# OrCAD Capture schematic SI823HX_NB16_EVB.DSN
size C; title: Si823Hx-NB16 Customer Evaluation Board - Schematic; rev: 1.0; note: SI823HX_NB16_EVB
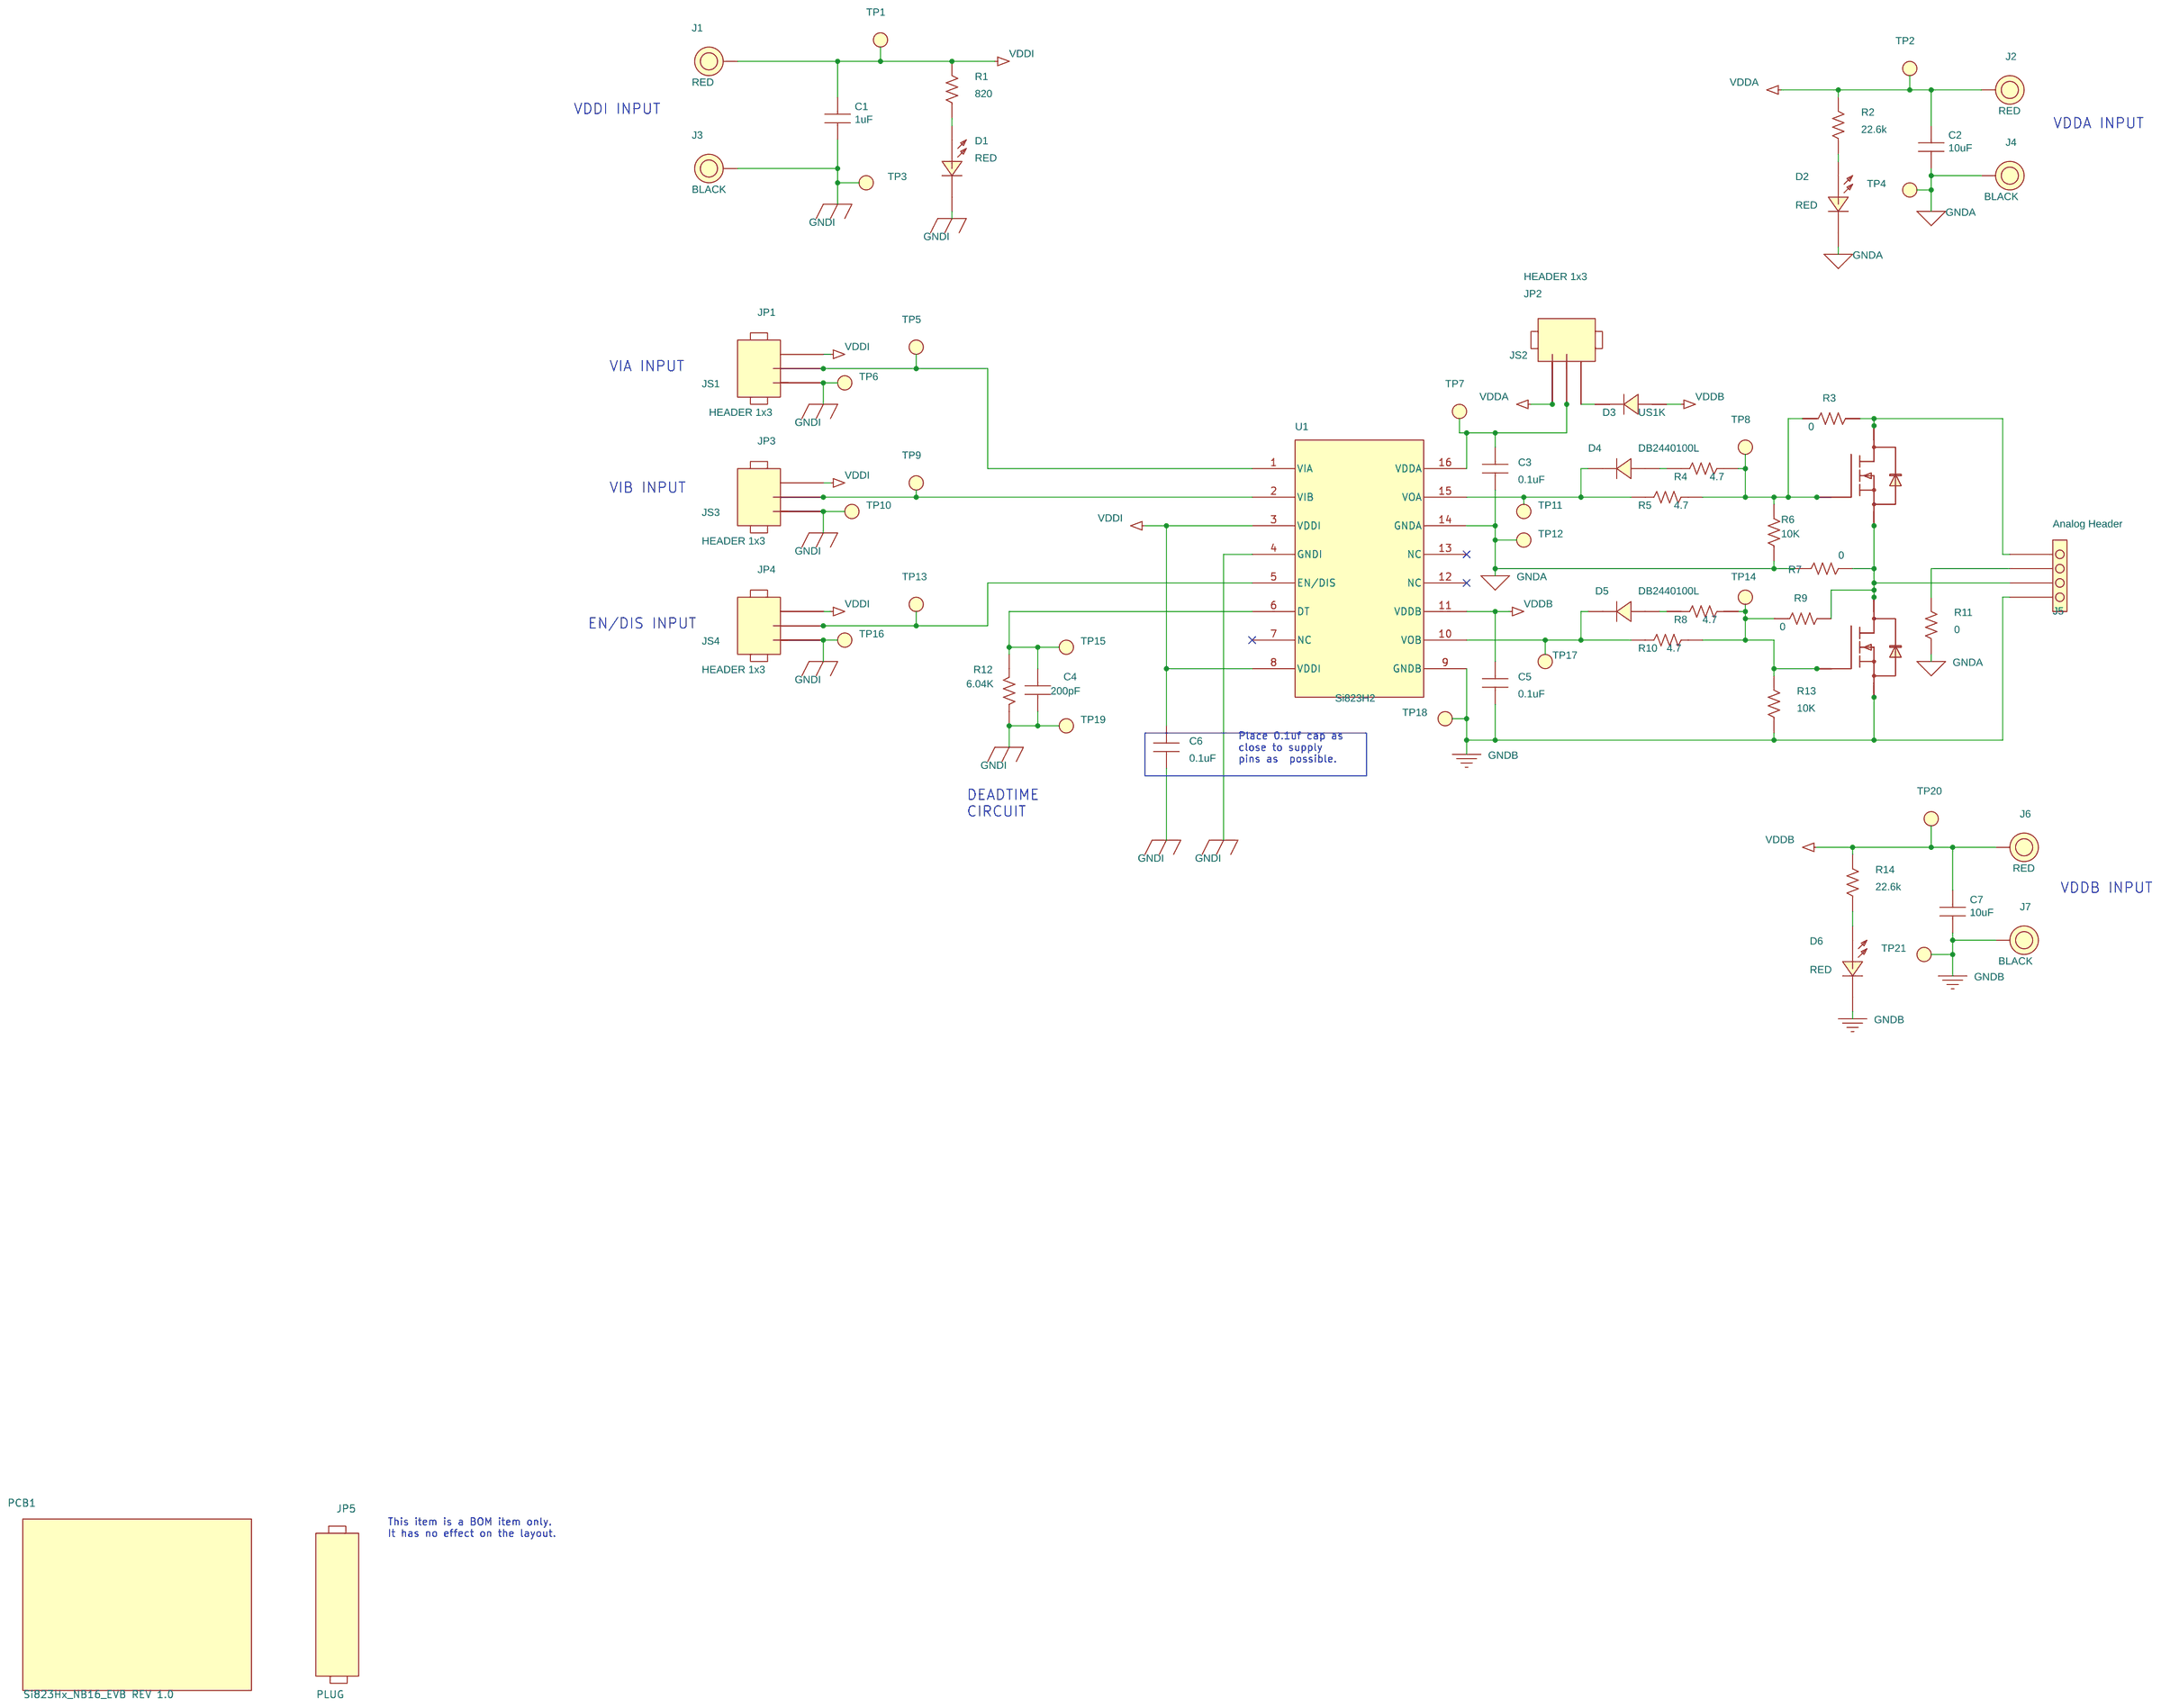
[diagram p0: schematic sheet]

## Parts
C1  1uF  [C0805]
C2  10uF  [C1210]
C3  0.1uF  [C1206]
C4  200pF  [C0805]
C5  0.1uF  [C1206]
C6  0.1uF  [C0805]
C7  10uF  [C1210]
D1  RED  [LED0603-KA]
D2  RED  [LED0603-KA]
D3  US1K  [DO-214AC]
D4  DB2440100L  [SOD-128]
D5  DB2440100L  [SOD-128]
D6  RED  [LED0603-KA]
J1  RED  [BINDING-POST]
J2  RED  [BINDING-POST]
J3  BLACK  [BINDING-POST]
J4  BLACK  [BINDING-POST]
J5  Analog Header  [CON1X4-1757268]
J6  RED  [BINDING-POST]
J7  BLACK  [BINDING-POST]
JP1  HEADER 1x3  [CONN-1X3]
JP2  HEADER 1x3  [CONN-1X3]
JP3  HEADER 1x3  [CONN-1X3]
JP4  HEADER 1x3  [CONN-1X3]
JP5  PLUG
JS1  Jumper Shunt  [SHUNT]
JS2  Jumper Shunt  [SHUNT]
JS3  Jumper Shunt  [SHUNT]
JS4  Jumper Shunt  [SHUNT]
PCB1  Si823Hx_NB16_EVB REV 1.0  [N/A]
R1  820  [R0402]
R2  22.6k  [R0402]
R3  0  [R0805]
R4  4.7  [R0805]
R5  4.7  [R0805]
R6  10K  [R0805]
R7  0  [R0805]
R8  4.7  [R0805]
R9  0  [R0805]
R10  4.7  [R0805]
R11  0  [R0805]
R12  6.04K  [R0805]
R13  10K  [R0805]
R14  22.6k  [R0402]
TP1  WHITE  [TESTPOINT]
TP2  WHITE  [TESTPOINT]
TP3  WHITE  [TESTPOINT]
TP4  WHITE  [TESTPOINT]
TP5  WHITE  [TESTPOINT]
TP6  WHITE  [TESTPOINT]
TP7  WHITE  [TESTPOINT]
TP8  WHITE  [TESTPOINT]
TP9  WHITE  [TESTPOINT]
TP10  WHITE  [TESTPOINT]
TP11  WHITE  [TESTPOINT]
TP12  WHITE  [TESTPOINT]
TP13  WHITE  [TESTPOINT]
TP14  WHITE  [TESTPOINT]
TP15  WHITE  [TESTPOINT]
TP16  WHITE  [TESTPOINT]
TP17  WHITE  [TESTPOINT]
TP18  WHITE  [TESTPOINT]
TP19  WHITE  [TESTPOINT]
TP20  WHITE  [TESTPOINT]
TP21  WHITE  [TESTPOINT]
U1  Si823H2  [SO16N6.0P1.27]
U3  SPD01N60C3  [DPAK-G2SD]
U4  IRF520  [TO-220_ALT]
U5  SPD01N60C3  [DPAK-G2SD]
U6  IRF520  [TO-220_ALT]

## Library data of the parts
C1 = CAP_NP: CAP, 1uF, 50V, ±10%, X7R, 0805; Manufacturer: Samsung; ManufacturerPN: CL21B105KBFNNNE; Part_Type: CAP/NP/MLCC; SiLabsPN: C0805X7R500-105K; Tolerance: ±10%; Type: X7R; Voltage: 50V; Datasheet: CL21B105KBFNNNE.pdf
C2 C7 = CAP_NP: CAP, 10uF, 50V, ±20%, X7R, 1210; Manufacturer: Venkel; ManufacturerPN: C1210X7R500-106M; Part_Type: CAP/NP/MLCC; SiLabsPN: C1210X7R500-106M; Tolerance: ±20%; Type: X7R; Voltage: 50V; Datasheet: PID_C.pdf
C3 C5 = CAP_NP: CAP, 0.1uF, 100V, ±20%, X7R, 1206; Manufacturer: Venkel; ManufacturerPN: C1206X7R101-104M; Part_Type: CAP/NP/MLCC; SiLabsPN: C1206X7R101-104M; Tolerance: ±20%; Type: X7R; Voltage: 100V; Datasheet: PID_C.pdf
C4 = CAP_NP: CAP, 200pF, 50V, ±10%, C0G, 0805; Manufacturer: Venkel; ManufacturerPN: C0805C0G500-201K; Part_Type: CAP/NP/MLCC; SiLabsPN: C0805C0G500-201K; Tolerance: ±10%; Type: C0G; Voltage: 50V; Datasheet: PID_C.pdf
C6 = CAP_NP: CAP, 0.1uF, 50V, ±10%, X7R, 0805; Manufacturer: Venkel; ManufacturerPN: C0805X7R500-104K; Part_Type: CAP/NP/MLCC; SiLabsPN: C0805X7R500-104K; Tolerance: ±10%; Type: X7R; Voltage: 50V; Datasheet: PID_C.pdf
D1 D2 D6 = LED: LED, RED, 631nM, 20mA, 2V, 54mcd, 0603; Manufacturer: LITE-ON TECHNOLOGY CORP; ManufacturerPN: LTST-C190KRKT; Part_Type: OPTO/LED; SiLabsPN: LTST-C190KRKT; Datasheet: P_100_LTST-C190KRKT.pdf
D3 = DIODE: DIO, SWITCH, ULTRA FAST, 800V, 1.0A, SMA; DISTRIBUTOR: Digi-Key; DIST_PN: US1K-FDICT-ND; MFG: Diodes Inc; MFG_PartNum: US1K-13-F; Manufacturer: Diodes Inc.; ManufacturerPN: US1K-13-F; Part_Type: DIO/SMT; Rating: 1.0A; SiLabsPN: US1K-13-F; Type: Switch, Ultra Fast; Voltage: 800V; Datasheet: ds16008.pdf
D4 D5 = DIODE: DIO, FAST, 40V, 1.0A, SOD-128; Manufacturer: Panasonic; Part_Type: DIO/SMT; Rating: 1.0A; Type: FAST; Voltage: 40V; Datasheet: DB2440100L.pdf
J1 = BINDING-POST: BINDING POST, Insulated, RED; Manufacturer: Johnson/Emerson; ManufacturerPN: 111-0702-001; Part_Type: CON; Rating: 15A; SiLabsPN: 111-0702-001; Silk: VDDI+; Type: BANANA; Datasheet: 111-0702-001.pdf
J2 = BINDING-POST: BINDING POST, Insulated, RED; Manufacturer: Johnson/Emerson; ManufacturerPN: 111-0702-001; Part_Type: CON; Rating: 15A; SiLabsPN: 111-0702-001; Silk: VDDA; Type: BANANA; Datasheet: 111-0702-001.pdf
J3 = BINDING-POST: BINDING POST, Insulated, BLACK; Manufacturer: Johnson/Emerson; ManufacturerPN: 111-0703-001; Part_Type: CON; Rating: 15A; SiLabsPN: 111-0703-001; Silk: GNDI; Type: BANANA; Datasheet: 111-0703-001.pdf
J4 = BINDING-POST: BINDING POST, Insulated, BLACK; Manufacturer: Johnson/Emerson; ManufacturerPN: 111-0703-001; Part_Type: CON; Rating: 15A; SiLabsPN: 111-0703-001; Silk: GNDA; Type: BANANA; Datasheet: 111-0703-001.pdf
J5 = ANALOG-HDR1X4: CONN, TERM HDR 4POS, 5.08MM, RT PCB; Manufacturer: PHOENIX CONTACT; ManufacturerPN: 1757268; Part_Type: CON; SiLabsPN: 1757268; Silk: VDD; Type: TERM HDR; Datasheet: 1757268.pdf
J6 = BINDING-POST: BINDING POST, Insulated, RED; Manufacturer: Johnson/Emerson; ManufacturerPN: 111-0702-001; Part_Type: CON; Rating: 15A; SiLabsPN: 111-0702-001; Silk: VDDB; Type: BANANA; Datasheet: 111-0702-001.pdf
J7 = BINDING-POST: BINDING POST, Insulated, BLACK; Manufacturer: Johnson/Emerson; ManufacturerPN: 111-0703-001; Part_Type: CON; Rating: 15A; SiLabsPN: 111-0703-001; Silk: GNDB; Type: BANANA; Datasheet: 111-0703-001.pdf
JP1-JP4 = CONN_HEADER_3: Header, 3x1, 0.1in pitch, Tin Plated; Manufacturer: Samtec; ManufacturerPN: TSW-103-07-T-S; Part_Type: CON/HEADER; SiLabsPN: TSW-103-07-T-S; Type: Header; Datasheet: TSW_TH.PDF
JP5 = CONN_TRBLK_9_MATE: CONN, TERM BLOCK, 4POS PLUG, 5.08MM; Manufacturer: Phoenix Contact; ManufacturerPN: 1757035; Part_Type: CON; SiLabsPN: 1757035; Type: TERM BLK; Datasheet: 1757035.pdf
JS1-JS4 = JMPR_SHUNT_SHORT_SIDES: Shunt, 1x2, 0.1in pitch, Tin plating; Manufacturer: Samtec; ManufacturerPN: SNT-100-BK-T; Part_Type: CON/SHUNT; SiLabsPN: SNT-100-BK-T; Type: Shunt; Datasheet: SNT.pdf
PCB1 = PCB: PCB, BARE BOARD, Si823Hx_NB16_EVB REV 1.0; Manufacturer: Skyworks; Part_Type: PCB/APS/Isolation; Type: BARE PCB
R1 = RES: RES, 820 Ohm, 1/16W, ±1%, ThickFilm, 0402; Manufacturer: Venkel; ManufacturerPN: CR0402-16W-8200FT; Part_Type: RES/SMT/ThickFilm; Rating: 1/16W; SiLabsPN: CR0402-16W-8200F; Tolerance: ±1%; Type: ThickFilm; Datasheet: PID_CR.pdf
R2 R14 = RES: RES, 22.6k, 1/16W, ±1%, ThickFilm, 0402; Manufacturer: Venkel; ManufacturerPN: CR0402-16W-2262F; Part_Type: RES/SMT/ThickFilm; Rating: 1/16W; SiLabsPN: CR0402-16W-2262F; Tolerance: ±1%; Type: ThickFilm; Datasheet: PID_CR.pdf
R3 R7 R9 R11 = RES: RES, 0 Ohm, 2A, ThickFilm, 0805; Manufacturer: Venkel; ManufacturerPN: CR0805-10W-000; Part_Type: RES/SMT/ThickFilm; Rating: 2A; SiLabsPN: CR0805-10W-000; Type: ThickFilm; Datasheet: PID_CR.pdf
R4 R5 R8 R10 = R: RES, 4.7 Ohm, 1/10W, ±5%, ThickFilm, 0805; Manufacturer: Venkel; ManufacturerPN: CR0805-10W-4R7J; Part_Type: RES/SMT/ThickFilm; Rating: 1/10W; SiLabsPN: CR0805-10W-4R7J; Tolerance: ±5%; Type: ThickFilm; Datasheet: PID_CR.pdf
R6 R13 = RES: RES, 10K, 1/8W, ±1%, ThickFilm, 0805; Manufacturer: Venkel; ManufacturerPN: CR0805-8W-1002F; Part_Type: RES/SMT/ThickFilm; Rating: 1/8W; SiLabsPN: CR0805-8W-1002F; Tolerance: ±1%; Type: ThickFilm; Datasheet: PID_CR.pdf
R12 = R: RES, 6.04K, 1/10W, ±1%, ThickFilm, 0805; DISTRIBUTOR: Digi-Key; DIST_PN: P150CCT-ND; MFG: Panasonic; MFG_PartNum: ERJ-6ENF1500V; Manufacturer: Venkel; ManufacturerPN: CR0805-10W-6041F; Part_Type: RES/SMT/ThickFilm; Rating: 1/10W; SiLabsPN: CR0805-10W-6041F; Tolerance: ±1%; Type: ThickFilm; Datasheet: PID_CR.pdf
TP1 = TEST_POINT: TESTPOINT, WHITE, PTH; Manufacturer: Kobiconn; ManufacturerPN: 151-201-RC; SiLabsPN: 151-201; Silk: VDDI; Type: Loop; Datasheet: KC-300780.pdf
TP2 = TEST_POINT: TESTPOINT, WHITE, PTH; Manufacturer: Kobiconn; ManufacturerPN: 151-201-RC; SiLabsPN: 151-201; Silk: VDDA; Type: Loop; Datasheet: KC-300780.pdf
TP3 TP6 TP10 TP16 TP19 = TEST_POINT: TESTPOINT, WHITE, PTH; Manufacturer: Kobiconn; ManufacturerPN: 151-201-RC; SiLabsPN: 151-201; Silk: GNDI; Type: Loop; Datasheet: KC-300780.pdf
TP4 TP12 = TEST_POINT: TESTPOINT, WHITE, PTH; Manufacturer: Kobiconn; ManufacturerPN: 151-201-RC; SiLabsPN: 151-201; Silk: GNDA; Type: Loop; Datasheet: KC-300780.pdf
TP5 = TEST_POINT: TESTPOINT, WHITE, PTH; Manufacturer: Kobiconn; ManufacturerPN: 151-201-RC; SiLabsPN: 151-201; Silk: VIA; Type: Loop; Datasheet: KC-300780.pdf
TP7 = TEST_POINT: TESTPOINT, WHITE, PTH; Manufacturer: Kobiconn; ManufacturerPN: 151-201-RC; SiLabsPN: 151-201; Type: Loop; Datasheet: KC-300780.pdf
TP8 = TEST_POINT: TESTPOINT, WHITE, PTH; Manufacturer: Kobiconn; ManufacturerPN: 151-201-RC; SiLabsPN: 151-201; Silk: VGA; Type: Loop; Datasheet: KC-300780.pdf
TP9 = TEST_POINT: TESTPOINT, WHITE, PTH; Manufacturer: Kobiconn; ManufacturerPN: 151-201-RC; SiLabsPN: 151-201; Silk: VIB; Type: Loop; Datasheet: KC-300780.pdf
TP11 = TEST_POINT: TESTPOINT, WHITE, PTH; Manufacturer: Kobiconn; ManufacturerPN: 151-201-RC; SiLabsPN: 151-201; Silk: VOA; Type: Loop; Datasheet: KC-300780.pdf
TP13 = TEST_POINT: TESTPOINT, WHITE, PTH; Manufacturer: Kobiconn; ManufacturerPN: 151-201-RC; SiLabsPN: 151-201; Silk: EN/DIS; Type: Loop; Datasheet: KC-300780.pdf
TP14 = TEST_POINT: TESTPOINT, WHITE, PTH; Manufacturer: Kobiconn; ManufacturerPN: 151-201-RC; SiLabsPN: 151-201; Silk: VGB; Type: Loop; Datasheet: KC-300780.pdf
TP15 = TEST_POINT: TESTPOINT, WHITE, PTH; Manufacturer: Kobiconn; ManufacturerPN: 151-201-RC; SiLabsPN: 151-201; Silk: DT; Type: Loop; Datasheet: KC-300780.pdf
TP17 = TEST_POINT: TESTPOINT, WHITE, PTH; Manufacturer: Kobiconn; ManufacturerPN: 151-201-RC; SiLabsPN: 151-201; Silk: VOB; Type: Loop; Datasheet: KC-300780.pdf
TP18 TP21 = TEST_POINT: TESTPOINT, WHITE, PTH; Manufacturer: Kobiconn; ManufacturerPN: 151-201-RC; SiLabsPN: 151-201; Silk: GNDB; Type: Loop; Datasheet: KC-300780.pdf
TP20 = TEST_POINT: TESTPOINT, WHITE, PTH; Manufacturer: Kobiconn; ManufacturerPN: 151-201-RC; SiLabsPN: 151-201; Silk: VDDB; Type: Loop; Datasheet: KC-300780.pdf
U1 = SI823HX-NB16: IC, ISOdriver, 4A, 2.5KV, HS/LS Input, SO16; Manufacturer: Skyworks; ManufacturerPN: Si823H2AB-IS1; Part_Type: IC/SILABS/POWER; Rating: 2500 VRMS; SiLabsPN: Si823H2AB-IS1; Type: ISOdriver; Voltage: 30V; Datasheet: Si823Hx-DataSheet.pdf
U3 U5 = NFET_PWR_4PIN: TRANSISTOR, MOSFET, N-CHNL, 650V, 800mA, DPAK; Manufacturer: Infineon Technologies; Part_Type: XTR/FET; Rating: 800mA; Type: N-CHNL; Voltage: 650V; Datasheet: SPD_U01N60C3_Rev.2.4.pdf
U4 U6 = NFET_PWR_4PIN: TRANSISTOR, MOSFET, N-CHNL, 100V, 9.2A, TO-220AB; FPLIST: TO-220,TO-220_ALT; Manufacturer: Vishay; ManufacturerPN: IRF520PbF; Part_Type: XTR/FET; Rating: 9.2A; SiLabsPN: IRF520PbF; Type: N-CHNL; Voltage: 100V; Datasheet: IRF520.pdf

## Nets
GNDA: C2.2 C3.2 D2.K(CATHODE) J4.1(BP) R6.1 R7.1 R11.1 TP4.1(Point) TP12.1(Point) U1.14(GNDA)
GNDB: C5.2 C7.2 D6.K(CATHODE) J5.1 J7.1(BP) R13.1 TP18.1(Point) TP21.1(Point) U1.9(GNDB) U5.S(SOURCE) U6.S(SOURCE)
GNDI: C1.2 C4.2 C6.2 D1.K(CATHODE) J3.1(BP) JP1.3 JP3.3 JP4.3 JS1.1 JS3.1 JS4.1 R12.2 TP3.1(Point) TP6.1(Point) TP10.1(Point) TP16.1(Point) TP19.1(Point) U1.4(GNDI)
VDDA: C2.1 J2.1(BP) JP2.3 JS2.2 R2.2 TP2.1(Point)
VDDB: C5.1 C7.1 D3.A(ANODE) J6.1(BP) R14.2 TP20.1(Point) U1.11(VDDB)
VDDI: C1.1 C6.1 J1.1(BP) JP1.1 JP3.1 JP4.1 R1.2 TP1.1(Point) U1.3(VDDI) U1.8(VDDI)
N17710773: JP1.2 JS1.2 TP5.1(Point) U1.1(VIA)
N17720180: C3.1 JP2.2 JS2.1 TP7.1(Point) U1.16(VDDA)
N17722605: C4.1 R12.1 TP15.1(Point) U1.6(DT)
N18521254: JP3.2 JS3.2 TP9.1(Point) U1.2(VIB)
N18523544: JP4.2 JS4.2 TP13.1(Point) U1.5(EN/DIS)
N18581125: D4.K(CATHODE) R5.1 TP11.1(Point) U1.15(VOA)
N18608236: D5.K(CATHODE) R10.1 TP17.1(Point) U1.10(VOB)
N18614444: D4.A(ANODE) R4.1
N18614450: R3.1 R4.2 R5.2 R6.2 TP8.1(Point) U3.G(GATE) U4.G(GATE)
N18614484: D5.A(ANODE) R8.1
N18614487: R8.2 R9.1 R10.2 R13.2 TP14.1(Point) U5.G(GATE) U6.G(GATE)
N18615977: D1.A(ANODE) R1.1
N18616431: D2.A(ANODE) R2.1
N18616592: D6.A(ANODE) R14.1
N18617713: J5.2 R7.2 R9.2 U3.S(SOURCE) U4.S(SOURCE) U5.4(DRAIN) U5.D U6.4(DRAIN) U6.D
N18620480: J5.4 R3.2 U3.4(DRAIN) U3.D U4.4(DRAIN) U4.D
N18621528: J5.3 R11.2
N18623026: D3.K(CATHODE) JP2.1

Not connected (* = marked no-connect by the designer): U1 7(NC)* 12(NC)* 13(NC)*

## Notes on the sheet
- VDDI INPUT
- VDDA INPUT
- VIA INPUT
- VIB INPUT
- EN/DIS INPUT
- Place 0.1uf cap as
  close to supply
  pins as  possible.
- DEADTIME
  CIRCUIT
- VDDB INPUT
- This item is a BOM item only.
  It has no effect on the layout.
